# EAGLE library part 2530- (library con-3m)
3M (TM) Pak 100 4-Wall Header Source: 3M
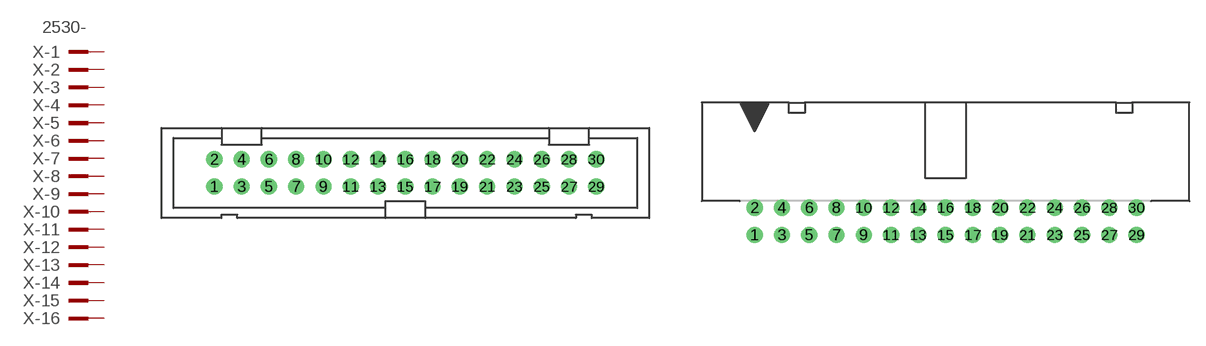
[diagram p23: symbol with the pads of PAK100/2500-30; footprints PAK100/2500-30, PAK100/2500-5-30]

Designator prefix X; gates -1=PINV -2=PIN -3=PIN -4=PIN -5=PIN -6=PIN -7=PIN -8=PIN -9=PIN -10=PIN -11=PIN -12=PIN -13=PIN -14=PIN -15=PIN -16=PIN -17=PIN -18=PIN -19=PIN -20=PIN -21=PIN -22=PIN -23=PIN -24=PIN -25=PIN -26=PIN -27=PIN -28=PIN -29=PIN -30=PIN

## 2530- (OC_FARNELL: 1788688; OC_NEWARK: unknown)  [PAK100/2500-30]
1  -1:KL  pas
2  -2:KL  pas
3  -3:KL  pas
4  -4:KL  pas
5  -5:KL  pas
6  -6:KL  pas
7  -7:KL  pas
8  -8:KL  pas
9  -9:KL  pas
10  -10:KL  pas
11  -11:KL  pas
12  -12:KL  pas
13  -13:KL  pas
14  -14:KL  pas
15  -15:KL  pas
16  -16:KL  pas
17  -17:KL  pas
18  -18:KL  pas
19  -19:KL  pas
20  -20:KL  pas
21  -21:KL  pas
22  -22:KL  pas
23  -23:KL  pas
24  -24:KL  pas
25  -25:KL  pas
26  -26:KL  pas
27  -27:KL  pas
28  -28:KL  pas
29  -29:KL  pas
30  -30:KL  pas

## 2530-5 (MF: 3M; MPN: N2530-5002RB; OC_FARNELL: 1788686; OC_NEWARK: 82K9519)  [PAK100/2500-5-30]
Pads as for PAK100/2500-30

## Footprint PAK100/2500-30 (pad centres in mm)
3M (TM) Pak 100 4-Wall Header Straight Source: 3M
drill 1 pad 1.422 round: 1 -17.78,-1.27; 2 -17.78,1.27; 3 -15.24,-1.27; 4 -15.24,1.27; 5 -12.7,-1.27; 6 -12.7,1.27; 7 -10.16,-1.27; 8 -10.16,1.27; 9 -7.62,-1.27; 10 -7.62,1.27; 11 -5.08,-1.27; 12 -5.08,1.27; 13 -2.54,-1.27; 14 -2.54,1.27; 15 0,-1.27; 16 0,1.27; 17 2.54,-1.27; 18 2.54,1.27; 19 5.08,-1.27; 20 5.08,1.27; 21 7.62,-1.27; 22 7.62,1.27; 23 10.16,-1.27; 24 10.16,1.27; 25 12.7,-1.27; 26 12.7,1.27; 27 15.24,-1.27; 28 15.24,1.27; 29 17.78,-1.27; 30 17.78,1.27

## Footprint PAK100/2500-5-30 (pad centres in mm)
3M (TM) Pak 100 4-Wall Header Right Angle Source: 3M
drill 1 pad 1.422 round: 1 -17.78,-1.27; 2 -17.78,1.27; 3 -15.24,-1.27; 4 -15.24,1.27; 5 -12.7,-1.27; 6 -12.7,1.27; 7 -10.16,-1.27; 8 -10.16,1.27; 9 -7.62,-1.27; 10 -7.62,1.27; 11 -5.08,-1.27; 12 -5.08,1.27; 13 -2.54,-1.27; 14 -2.54,1.27; 15 0,-1.27; 16 0,1.27; 17 2.54,-1.27; 18 2.54,1.27; 19 5.08,-1.27; 20 5.08,1.27; 21 7.62,-1.27; 22 7.62,1.27; 23 10.16,-1.27; 24 10.16,1.27; 25 12.7,-1.27; 26 12.7,1.27; 27 15.24,-1.27; 28 15.24,1.27; 29 17.78,-1.27; 30 17.78,1.27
